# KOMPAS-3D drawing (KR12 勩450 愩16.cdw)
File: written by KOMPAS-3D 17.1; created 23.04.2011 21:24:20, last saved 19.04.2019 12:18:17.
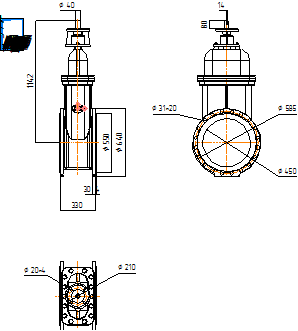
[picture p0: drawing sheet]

Sheet 1: A4, portrait

Title block, sheet 1: name: KR12 Ду450 Ру16; material: Внимание! Данный продукт является объектом авторского права ООО «Торговый Дом АДЛ». / Запрещается изменение, копирование, распространение / (в том числе путем копирования на другие сайты и ресурсы в Интернете) / или любое иное использование информации и объектов без предварительного / согласия правообладателя (ООО «Торговый Дом АДЛ»).; scale: 1:1; sheets: 1; organisation: ООО "Торговый дом АДЛ"; sheet format: A4; stored path: \\adlc.lan\data\АДЛ_ПКД\3D-модели\ADL production\Клиновые задвижки серии KR ГРАНАР\Клиновые задвижки KR12\KOMPAS 2D\KR12 Ду450 Ру16.cdw

Views: Спереди 1, Проекционный вид 3
Dimensions and other numbers on the sheet: 450; 585; 31; 550; 640; 14; 40; 80; 1142; 210; 20; 330; 30; 4; 1:1; 1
